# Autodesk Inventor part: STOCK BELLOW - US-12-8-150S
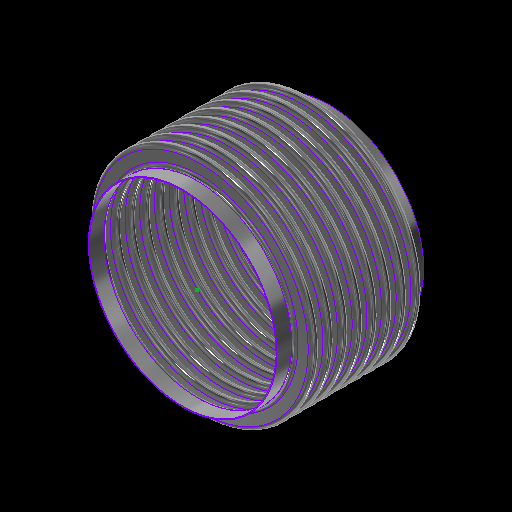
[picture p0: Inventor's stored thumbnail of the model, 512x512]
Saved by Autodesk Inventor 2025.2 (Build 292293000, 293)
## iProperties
Category: 16 GA (0.060 THICK)
RuleStatus: InUse
Created: 2024-01
Part Number: STOCK BELLOW - US-12-8-150S
Project: =STOCK BELLOWS: <Stock Number><SFILL>
Material: ASTM A240-304
Description: =STOCK BELLOWS: <Stock Number>, <SID_> I.D., <SOD_> O.D., <SPLY_> PLY, <Category>, <SNET_CONS> CONS.<PITCH_><STANGENT_> TANGENT<SFILL>
Document SubType Name: Sheet Metal
Designer: GS
Stock Number: U.S-12-8-150S
Surface Area: 14528.9 cm^2
Volume: 1099.98 cm^3
Sheet Metal Rule: Default
Appearance: STAINLESS STEEL
Mass: 8862.87 g
Density: 8.05729 g/cm^3
THK: 0.036
ID: 3.500
OD: 4.250
CONS_: 2
PITCH: 0.500
TANGENT: 0.500
BELLOWS_UPSET: 0.000
d79: 1.000
d82: 1.000
d83: 26.000
d84: 24.000
d174: 8
d214: 8
STHK_: 0.060
SID_: 12.750
SOD_: 15.250
SPITCH_: 1.000
STANGENT__: 1.000
SBELLOWS_UPSET_: 0.000
SDIFF_TAN: 1.000
d252: 2
d275: 2
d287: 0.050
d289: 0.500
d290: 0.000
SOD_NECK: 12 7/8
PLY: 1
PSET: 4.178
PBAR: 1.035
COUNTER: 1.500
NET_TUBE: 3.071
CONS: 2
S_CONS: 0
NET_CONS: 2
ID_M: 88.90 mm
OD_M: 107.95 mm
THK_M: 0.91 mm
ID_U: 3.500 in
OD_U: 4.250 in
THK_U: 0.036 in
TANGENT2: 0.500
TAN_TO_TAN: 1.000 in
d80: 2.571
d81: 10
SID: 2.375
SCONS_: 8
SPITCH: 0.250
STANGENT_: 1.000
SBELLOWS_UPSET: 0.000
SNET_CONS: 8
SS_CONS: 0
SCONS: 8
d190: 8
d191: 1
d192: 1
d193: 8
d194: 0
SIZE: 12.00
PRESSURE: 150
d230: 8
STANGENT: 4.000
SPLY_: 1
d233: 8
d234: 0
d263: 2
d265: 1
d268: 2
d269: 0
d286: 2
d288: 1
d291: 2
d292: 0
SREROLL: 0.750
BLETP: 0.000 ul
PRES_Copy: 85
MATTABLE: 20 GA (0.036 THICK)
PART_NUMBER: U.S-12-8-150S
PITCH_: =, <SPITCH_> PITCH,
CFILL: .
SFILL: .
MESH: ,
COMP: 1.54
EXT: 0.77
LAT: 0.29
ANG: 573
ASR: 3532
LSR: 14601
ANSR: 1359
PRES: 150
COMPM: 15.4
EXTM: 7.7
LATM: 2.90
ASRM: 618.559
PRESM: 10.342
LSRM: 2557.073
ANSRM: 238.002
TEMPMIN: 20
TEMPMAX: 800
TEMPMINM: -7
TEMPMAXM: 427
WEIGHTM: 8.863
WEIGHT: 19.539
Author: GS
Keywords: 20 GA (0.036 THICK)
Comments: =STOCK BELLOW - <STOCK NUMBER>
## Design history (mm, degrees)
sketch "Sketch2"
  geometry: L1 (0, -177.245)-(0, 562.856) reference; L2 (45.364, 0)-(44.45, 0); L3 (48.082, -2.718)-(50.343, -2.718); L4 (48.082, -3.632)-(50.343, -3.632); L5 (50.343, -9.982)-(48.082, -9.982); L6 (50.343, -9.068)-(48.082, -9.068); L7 (45.364, -12.7)-(44.45, -12.7); L8 (48.082, 0)-(48.082, -12.7); L9 (50.343, -6.35)-(53.975, -6.35); L10 (44.45, 0)-(44.45, -12.7); L11 (20.376, 102.841)-(20.376, 101.926); L12 (58.262, 457.127)-(58.262, 349.177); L13 (58.262, 444.427)-(58.262, 336.477); L14 (93.133, -58.817)-(93.133, -71.517); L15 (118.746, -66.401)-(118.746, -66.401); L16 (50.343, -9.068)-(50.343, -9.982); L17 (48.082, -9.068)-(48.082, -9.982); L18 (48.082, -9.525)-(50.343, -9.525); L19 (53.975, 0)-(53.975, -12.7); L20 (-50.343, -9.068)-(-50.343, -9.982); L21 (-50.343, -2.718)-(-48.082, -2.718); L22 (-50.343, -3.632)-(-48.082, -3.632); L23 (-48.082, -9.068)-(-50.343, -9.068); L24 (-50.343, -9.525)-(-48.082, -9.525); L25 (-48.082, -9.982)-(-50.343, -9.982); L26 (-48.082, -9.068)-(-48.082, -9.982); L27 (-44.45, 0.653)-(-44.45, -12.047); L28 (-48.082, -6.35)-(-44.45, -6.35); L29 (-50.343, 0.653)-(-50.343, -12.7); L30 (-53.061, 0)-(-53.975, 0); L31 (-53.975, 0)-(-53.975, -12.7); L32 (-53.061, -12.7)-(-53.975, -12.7); A1 r 2.718 centre (48.082, 0) between (45.364, 0) and (48.082, -2.718); A2 r 3.632 centre (48.082, 0) between (44.45, 0) and (48.082, -3.632); A3 r 3.632 centre (50.343, -6.35) between (50.343, -9.982) and (50.343, -2.718); A4 r 2.718 centre (50.343, -6.35) between (50.343, -9.068) and (50.343, -3.632); A5 r 2.718 centre (48.082, -12.7) between (48.082, -9.982) and (45.364, -12.7); A6 r 3.632 centre (48.082, -12.7) between (48.082, -9.068) and (44.45, -12.7); A7 r 3.175 centre (50.343, -6.35) between (50.343, -9.525) and (53.518, -6.35); A8 r 3.175 centre (48.082, -12.7) between (48.082, -9.525) and (44.907, -12.7); A9 r 2.718 centre (-50.343, -12.7) between (-50.343, -9.982) and (-53.061, -12.7); A10 r 2.718 centre (-48.082, -6.35) between (-48.082, -9.068) and (-48.082, -3.632); A11 r 3.175 centre (-48.082, -6.35) between (-48.082, -9.525) and (-44.907, -6.35); A12 r 3.632 centre (-48.082, -6.35) between (-48.082, -9.982) and (-48.082, -2.718); A13 r 3.175 centre (-50.343, -12.7) between (-50.343, -9.525) and (-53.518, -12.7); A14 r 3.632 centre (-50.343, -12.7) between (-50.343, -9.068) and (-53.975, -12.7); A15 r 2.718 centre (-50.343, 0) between (-53.061, 0) and (-50.343, -2.718); A16 r 3.632 centre (-50.343, 0) between (-53.975, 0) and (-50.343, -3.632); 10 further points
  constraints: 62 end point, 38 point on circle, 20 tangent, 16 centre point, 12 parallel, 9 midpoint, 7 vertical, 6 coincident, 6 concentric, 6 point on line, 4 equal radius, 4 perpendicular, 3 horizontal, 1 collinear, 1 horizontal alignment, 10 other
  dimensions: "THK" = 0.9144 distance of L11.start L11.end; "ID" = 88.9 distance of L11.end point (20.376, 13.026); "OD" = 107.95 distance of L12.start L12.end; "PITCH" = 12.7 distance of L12.start L13.start; "TANGENT" = 12.7 distance of L14.start L14.end; "BELLOWS_UPSET" = 0 distance of L15.start L15.end; "d43" = 88.9 diameter of L10 L1 (= ID); "d44" = 107.95 diameter of L9.end L1 (= OD); "d45" = 0.9144 distance between parallel lines of L5 L6 (computed from THK, PLY); "d46" = 3.6322 radius of A3 (computed from PITCH, THK, PLY); "UPSET_PITCH" = 12.7 distance of L2.end L7.end (derived); "SIDEWALL_ANGLE" = 360 deg dimension on L3 L9 (derived); "CON_GAP" = 5.4356 distance of point (48.082, -9.068) point (48.082, -3.632) (derived); "TAN1" = 4.98728 dimension on A8 (derived); "TAN2" = 4.98728 dimension on A7 (derived); "LEG1" = 2.2606 distance of L18.start L18.end (derived); "d278" = 0.9144 distance between parallel lines of L25 L23 (derived); "d279" = 3.6322 radius of A12 (derived); "d280" = 12.7 distance of L30.end L31.end (derived); "d281" = 360 deg dimension on L21 L28 (derived); "d282" = 5.4356 distance of point (-50.343, -9.068) point (-50.343, -3.632) (derived); "d283" = 4.98728 dimension on A13 (derived); "d284" = 4.98728 dimension on A11 (derived); "d285" = 2.2606 distance of L24.start L24.end (derived); "d293" = 88.9 diameter of L27 L1 (derived); "d294" = 107.95 diameter of L31 L1 (derived)
  node "Sketch Rectangular Pattern1" dims "d31" = 25.4, "ID" = 88.9
  node "Sketch Rectangular Pattern2" dims "d39" = 25.4, "PITCH" = 12.7
revolve "CONS" stored, may be unused: angle "d48" = 90 deg
node "BELLOW MIDPLANE"
pattern_linear "Rectangular Pattern2" dims "d52" = 12.7 (= UPSET_PITCH)
sketch "Sketch5"
  geometry: C1 r 45.364 at (0, 0) reference; C2 r 44.45 at (0, 0) reference
extrude "TANGENT" new body sketch "Sketch5" distance "d53" = 12.7 (= TANGENT); taper "d54" = 0 deg
revolve "SAMETAN" stored, may be unused: angle "d65" = 90 deg
revolve "DIFFTAN" stored, may be unused: angle "d70" = 90 deg
sketch "Sketch9"
  geometry: L1 (53.319, 0)-(-53.319, 0) reference; L2 (0, -17.78)-(0, 17.78) reference; L3 (38.085, 0)-(-38.085, 0); L4 (38.085, -11.906)-(38.085, 11.906); L5 (25.385, -11.906)-(25.385, 11.906); L6 (13.15, 11.906)-(13.15, -11.906); L7 (-25.385, -11.906)-(-25.385, 11.906); L8 (-38.085, -11.906)-(-38.085, 11.906); L9 (37.291, -11.906)-(37.291, 11.906); L10 (38.085, -11.906)-(37.291, -11.906); L11 (38.085, 11.906)-(37.291, 11.906); L12 (13.546, 11.906)-(12.753, 11.906); L13 (12.753, 11.906)-(12.753, -11.906); L14 (12.753, -11.906)-(13.546, -11.906); L15 (13.546, -11.906)-(13.546, 11.906); L16 (-13.546, 11.906)-(-13.546, -11.906); L17 (-13.15, 11.906)-(-13.15, -11.906); L18 (-13.546, -11.906)-(-12.753, -11.906); L19 (-12.753, -11.906)-(-12.753, 11.906); L20 (-12.753, 11.906)-(-13.546, 11.906); L21 (-38.085, -11.906)-(-37.291, -11.906); L22 (-37.291, -11.906)-(-37.291, 11.906); L23 (-37.291, 11.906)-(-38.085, 11.906); L24 (-38.085, 11.906)-(-38.085, -11.906); L25 (38.085, -0.397)-(-38.085, -0.397); L26 (-38.085, -0.397)-(-38.085, 0.397); L27 (-38.085, 0.397)-(38.085, 0.397); L28 (38.085, 0.397)-(38.085, -0.397); L29 (-38.085, 11.906)-(38.085, 11.906); L30 (38.085, 11.906)-(38.085, 12.7); L31 (38.085, 12.7)-(-38.085, 12.7); L32 (-38.085, 12.7)-(-38.085, 11.906); L33 (38.085, -11.906)-(-38.085, -11.906); L34 (-38.085, -11.906)-(-38.085, -12.7); L35 (-38.085, -12.7)-(38.085, -12.7); L36 (38.085, -12.7)-(38.085, -11.906); 30 further points
  constraints: 68 end point, 13 midpoint, 13 parallel, 8 horizontal, 7 perpendicular, 6 equal length, 3 point on line, 2 vertical, 14 other
  dimensions: "d115" = 23.8125 distance of L4.start L4.end (derived); "d116" = 12.7 distance between parallel lines of L4 L5 (derived); "d117" = 12.23516 distance between parallel lines of L5 L6 (derived); "d125" = 38.53427 distance between parallel lines of L7 L6 (derived); "d127" = 12.7 distance between parallel lines of L8 L7 (derived); "d128" = 24.93516 distance between parallel lines of L6 L4 (derived); "d130" = 76.16943 distance between parallel lines of L8 L4 (derived); "RULER_THK" = 0.79375 distance between parallel lines of L4 L9; "d135" = 0.79375 distance of L13.end L14.end (derived); "d138" = 26.29911 distance of L13.end L16.end (derived); "d143" = 0.79375 distance of L22.end L8.end (derived); "d144" = 0.79375 distance between parallel lines of L27 L25 (derived)
extrude "RULER" join sketch "Sketch9" distance "d149" = 0.79375 (derived); taper "d150" = 0 deg
extrude "BARS" join sketch "Sketch9" distance "d151" = 0.79375 (derived); taper "d152" = 0 deg
pattern_linear "Rectangular Pattern4" dims "d155" = 26.29911 (derived)
sketch "Sketch13"
  geometry: L1 (93.149, -52.467)-(93.149, -77.867); L2 (163.449, 0)-(161.925, 0); L3 (163.449, -25.4)-(161.925, -25.4); L4 (186.563, -19.812)-(169.037, -19.812); L5 (186.563, -18.288)-(169.037, -18.288); L6 (186.563, -12.7)-(193.675, -12.7); L7 (169.037, -5.588)-(186.563, -5.588); L8 (169.037, 0)-(169.037, -25.4); L9 (161.925, 0)-(161.925, -25.4); L10 (58.254, -109.081)-(58.254, -496.431); L11 (58.254, -134.481)-(58.254, -521.831); L12 (58.254, -185.281)-(58.254, -572.631); L13 (58.254, -210.681)-(58.254, -598.031); L14 (58.254, -236.081)-(58.254, -623.431); L15 (58.254, -261.481)-(58.254, -648.831); L16 (58.254, -286.881)-(58.254, -674.231); L17 (58.254, -159.881)-(58.254, -547.231); L18 (20.376, 103.45)-(20.376, 101.926); L19 (169.037, -7.112)-(186.563, -7.112); L20 (0, -829.767)-(0, 258.986) reference; L21 (-38.735, 0)-(232.41, 0) reference; A1 r 5.588 centre (169.037, 0) between (163.449, 0) and (169.037, -5.588); A2 r 5.588 centre (169.037, -25.4) between (169.037, -19.812) and (163.449, -25.4); A3 r 7.112 centre (169.037, -25.4) between (169.037, -18.288) and (161.925, -25.4); A4 r 5.588 centre (186.563, -12.7) between (186.563, -18.288) and (186.563, -7.112); A5 r 7.112 centre (186.563, -12.7) between (186.563, -19.812) and (186.563, -5.588); A6 r 7.112 centre (169.037, 0) between (161.925, 0) and (169.037, -7.112); 6 further points; 1 other entity
  constraints: 38 end point, 15 point on circle, 9 tangent, 6 centre point, 6 parallel, 5 vertical alignment, 4 point on line, 4 vertical, 3 coincident, 3 concentric, 2 collinear, 2 equal radius, 1 horizontal, 1 perpendicular, 23 other
  dimensions: "SBELLOWS_UPSET_" = 0 distance of point (118.762, -66.401) point (118.762, -66.401); "STOTAL_THK_BELLOW__" = 1.524 distance between parallel lines of L4 L5 (derived); "d224" = 7.112 radius of A5 (derived); "d225" = 25.4 distance of L2.end L3.end (derived); "SSIDEWALL_ANGLE_" = 360 deg dimension on L7 L6 (derived); "SSCON_GAP_" = 11.176 distance of point (169.037, -18.288) point (169.037, -7.112) (derived); "d235" = 323.85 diameter of L9 L20 (derived); "d236" = 387.35 diameter of L6.end L20 (derived)
  node "Sketch Rectangular Pattern4" dims "d228" = 25.4
  node "Sketch Rectangular Pattern5" dims "d229" = 25.4
revolve "SBELLOW" stored, may be unused: angle "d197" = 90 deg
pattern_linear "Rectangular Pattern5" dims "d204" = 25.4 (derived)
revolve "STANGENT" stored, may be unused: angle "d240" = 90 deg
revolve "SSAMETAN" stored, may be unused: angle "d241" = 90 deg
revolve "SDIFFTAN" stored, may be unused: angle "d246" = 90 deg
revolve "INVCON" stored, may be unused: angle "d295" = 90 deg
pattern_linear "Rectangular Pattern6" dims "d298" = 12.7 (derived)
revolve "INVTANGENT" stored, may be unused: angle "d302" = 90 deg
revolve "INVSAMETAN" stored, may be unused: angle "d307" = 90 deg
revolve "INVDIFFTAN" stored, may be unused: angle "d312" = 90 deg
sketch "ID BELLOW MOUNT CALC"
  geometry: L1 (44.45, 0)-(38.1, 0); L2 (38.1, 0)-(38.1, 12.7); L3 (38.1, 12.7)-(44.45, 12.7); L4 (44.45, 12.7)-(44.45, 0); L5 (36.513, 12.7)-(35.598, 12.7); L6 (35.598, 12.7)-(35.598, 0); L7 (35.598, 0)-(36.513, 0); L8 (36.513, 0)-(36.513, 12.7); L9 (0, -2.54)-(0, 15.24) reference; L10 (-8.89, 0)-(53.34, 0) reference; 1 further point
  constraints: 16 end point, 5 parallel, 2 collinear, 2 horizontal, 2 perpendicular
  dimensions: "d314" = 12.7 distance of L5.end L6.end (derived); "d315" = 0.9144 distance of L5.start L5.end (derived); "IG" = 1.5875 distance between parallel lines of L2 L8; "PIPE_OD" = 88.9 diameter of L4 L9; "PIPE_WALL" = 6.35 distance of L2.end L3.end; "ID_MT_BELLOW" = 71.1962 diameter of L6 L9 (derived)
revolve "CFILL" stored, may be unused: angle "d320" = 90 deg
pattern_linear "Rectangular Pattern7" dims "d323" = 12.7 (derived)
revolve "SFILL" stored, may be unused: angle "d324" = 90 deg
pattern_linear "Rectangular Pattern8" dims "d327" = 25.4 (derived)
node "STOCK BELLOW MIDPLANE"
node "BELLOW"
sketch "Sketch6"
  geometry: L1 (-12.7, 45.364)-(0, 45.364); L2 (0, 45.364)-(0, 44.45); L3 (0, 44.45)-(-12.7, 44.45); L4 (-12.7, 44.45)-(-12.7, 45.364); L5 (10.16, 0)-(-60.96, 0) reference; L6 (-38.1, -89.422)-(-38.1, 153.44) reference; 1 further point
  constraints: 8 end point, 2 parallel, 1 horizontal, 1 perpendicular
  dimensions: "d61" = 12.7 distance of L2.end L3.end (derived); "d62" = 0.9144 distance of L1.end L2.end (derived); "d63" = 88.9 diameter of L3 L5 (derived); "d64" = 25.4 distance between parallel lines of L4 L6 (derived)
sketch "Sketch12"
  geometry: 1 further point
sketch "Sketch14"
  geometry: L1 (-25.4, 163.449)-(0, 163.449); L2 (0, 163.449)-(0, 161.925); L3 (0, 161.925)-(-25.4, 161.925); L4 (-25.4, 161.925)-(-25.4, 163.449); L5 (5.08, 0)-(-30.48, 0) reference; L6 (0, -32.69)-(0, 196.139) reference; 1 further point
  constraints: 8 end point, 2 parallel, 1 collinear, 1 horizontal, 1 perpendicular
  dimensions: "d237" = 1.524 distance of L3.end L1.start (derived); "d238" = 323.85 diameter of L3 L5 (derived); "d239" = 25.4 distance of L1.start L1.end (derived); "SOD_NECK" = 326.898 diameter of L1 L5 (derived)
sketch "Sketch15"
  geometry: L1 (-32.69, 0)-(196.139, 0) reference; L2 (161.925, -203.2)-(163.449, -203.2); L3 (163.449, -203.2)-(163.449, -228.6); L4 (163.449, -228.6)-(161.925, -228.6); L5 (161.925, -228.6)-(161.925, -203.2); L6 (0, -276.86)-(0, 60.96) reference; 1 further point
  constraints: 8 end point, 2 parallel, 1 horizontal, 1 perpendicular
  dimensions: "d205" = 25.4 distance of L4.end L2.start (derived); "d206" = 1.524 distance of L3.end L4.end (derived); "d207" = 323.85 diameter of L5 L6 (derived); "d208" = 203.2 distance between parallel lines of L1 L2 (derived)
node "TANGENT_"
node "SAME_TAN"
sketch "Sketch8"
  geometry: L1 (45.364, -25.4)-(44.45, -25.4); L2 (44.45, -25.4)-(44.45, -38.1); L3 (44.45, -38.1)-(45.364, -38.1); L4 (45.364, -38.1)-(45.364, -25.4); L5 (0, -48.26)-(0, 22.86) reference; L6 (-89.422, 0)-(153.44, 0) reference; 1 further point
  constraints: 8 end point, 2 parallel, 1 horizontal, 1 perpendicular
  dimensions: "d66" = 88.9 diameter of L2 L5 (derived); "TOTAL_THK_BELLOW" = 0.9144 distance of L2.end L3.end (derived); "d68" = 25.4 distance between parallel lines of L1 L6 (derived); "d69" = 12.7 distance of L1.end L2.end (derived)
node "DIFF_TAN"
node "Sketch Rectangular Pattern3" dims "d138" = 26.29911 (derived), "d141" = 25.4
node "SBELLOW_"
node "STANGENT_"
node "SSAME_TAN"
sketch "Sketch16"
  geometry: L1 (163.449, -203.2)-(161.925, -203.2); L2 (161.925, -203.2)-(161.925, -228.6); L3 (161.925, -228.6)-(163.449, -228.6); L4 (163.449, -228.6)-(163.449, -203.2); L5 (0, -276.86)-(0, 60.96) reference; L6 (-32.69, 0)-(196.139, 0) reference; 1 further point
  constraints: 8 end point, 2 parallel, 1 horizontal, 1 perpendicular
  dimensions: "SDIFF_TAN" = 25.4 distance of L3.end L1.start; "d243" = 1.524 distance of L2.end L3.end (derived); "d244" = 203.2 distance between parallel lines of L1 L6 (derived); "d245" = 323.85 diameter of L2 L5 (derived)
node "SDIFF_TAN"
body "Solid15"
sketch "Sketch17"
  geometry: L1 (53.975, 12.7)-(53.061, 12.7); L2 (53.061, 12.7)-(53.061, 0); L3 (53.061, 0)-(53.975, 0); L4 (53.975, 0)-(53.975, 12.7); L5 (0, -2.54)-(0, 15.24) reference; L6 (-10.795, 0)-(64.77, 0) reference; 2 further points
  constraints: 8 end point, 2 parallel, 1 horizontal, 1 midpoint, 1 perpendicular, 1 point on line
  dimensions: "INVTANGENT" = 12.7 distance of L3.end L1.start (derived); "d300" = 0.9144 distance of L1.start L1.end (derived); "d301" = 107.95 diameter of L4 L5 (derived)
body "Solid16"
sketch "Sketch18"
  geometry: L1 (53.975, -25.4)-(53.061, -25.4); L2 (53.061, -25.4)-(53.061, -38.1); L3 (53.061, -38.1)-(53.975, -38.1); L4 (53.975, -38.1)-(53.975, -25.4); L5 (-10.795, 0)-(64.77, 0) reference; L6 (0, -48.26)-(0, 22.86) reference; 1 further point
  constraints: 8 end point, 2 parallel, 1 horizontal, 1 perpendicular
  dimensions: "d303" = 25.4 distance between parallel lines of L1 L5 (derived); "d304" = 12.7 distance of L3.end L1.start (derived); "d305" = 0.9144 distance of L2.end L3.end (derived); "d306" = 107.95 diameter of L4 L6 (derived)
body "Solid17"
sketch "Sketch19"
  geometry: L1 (53.975, -25.4)-(53.061, -25.4); L2 (53.061, -25.4)-(53.061, -38.1); L3 (53.061, -38.1)-(53.975, -38.1); L4 (53.975, -38.1)-(53.975, -25.4); L5 (0, -48.26)-(0, 22.86) reference; L6 (-10.795, 0)-(64.77, 0) reference; 1 further point
  constraints: 8 end point, 2 parallel, 1 horizontal, 1 perpendicular
  dimensions: "d308" = 12.7 distance of L1.end L2.end (derived); "d309" = 107.95 diameter of L4 L5 (derived); "d310" = 0.9144 distance of L2.end L3.end (derived); "d311" = 25.4 distance between parallel lines of L1 L6 (derived)
body "Solid18"
body "Solid19"
body "Solid20"
other parameters: "BMPL" = -101.6, "PSET" = 106.1212 (computed from OD, THK, PLY) [user parameter], "PBAR" = 26.29911 (= 0.570796 x PITCH + OD - ID) [user parameter; used in 1 equation term], "COUNTER" = 15 [user parameter], "NET_TUBE" = 77.99823 (computed from CONS_, PBAR, TANGENT) [user parameter], "S_CONS" = 0 [user parameter; used in 1 equation term], "ID_M" = 88.9 (= ID) [user parameter], "OD_M" = 107.95 (= OD) [user parameter], "THK_M" = 0.9144 (= THK) [user parameter], "ID_U" = 88.9 (= ID) [user parameter], "OD_U" = 107.95 (= OD) [user parameter], "THK_U" = 0.9144 (= THK) [user parameter], "D_UNITS" = 0 [user parameter], "TANGENT2" = 12.7 [user parameter], "TAN_TO_TAN" = 25.4 [user parameter], "OD_NECK" = 90.7288 [user parameter], "d79" = 25.4, "d80" = 65.29823 [user parameter], "d82" = 25.4, "d83" = 660.4, "d84" = 609.6, "sa_0" = 4, "FRAME_THK" = 0.79375 [user parameter], "CON_FLAT" = 12.23516 [user parameter], "SID" = 60.325 [user parameter], "SPITCH" = 6.35 [user parameter], "STANGENT_" = 25.4 [user parameter], "SBELLOWS_UPSET" = 0 [user parameter], "SS_CONS" = 0 [user parameter], "STAN_TO_TAN_" = 203.2 [user parameter], "d100" = 1.524 [user parameter], "d191" = 25.4 [user parameter], "d194" = 0 [user parameter], "STANGENT" = 101.6 [user parameter], "d234" = 0 [user parameter], "SUPSET_PITCH_" = 25.4 [user parameter], "d269" = 0 [user parameter], "d287" = 1.27, "d289" = 12.7, "d290" = 0, "d292" = 0 [user parameter], "Thickness" = 3.048 (derived), "KFactor" = 4.4, "BendRadius" = 3.048 (derived), "BendReliefWidth" = 3.048 (derived), "BendReliefDepth" = 1.524 (derived), "CornerReliefSize" = 12.192 (derived), "SeamGap" = 0.00508, "MinimumRemnant" = 6.096 (derived), "TransitionRadius" = 3.048 (derived), "JacobiRadiusSize" = 3.048 (derived), "GapSize" = 3.048 (derived), "SREROLL" = 19.05 [user parameter], "CUR_STK_PITCH" = 25.4 [user parameter], "d328" = -101.6 (derived), "ASR" = 35320 [user parameter], "LSR" = 146010 [user parameter], "ANSR" = 13590 [user parameter], "BLETP" = 0 [user parameter], "ASRM" = 6185.5916 [user parameter], "PRESM" = 103.41975 [user parameter], "LSRM" = 25570.7313 [user parameter], "ANSRM" = 2380.0167 [user parameter], "TEMPMIN" = 2664.83333 [user parameter], "TEMPMAX" = 6998.16667 [user parameter], "TEMPMINM" = 2664.83333 [user parameter], "TEMPMAXM" = 6998.16667 [user parameter], "WEIGHT" = 88.62868 [user parameter], "WEIGHTM" = 0.08863 [user parameter]
